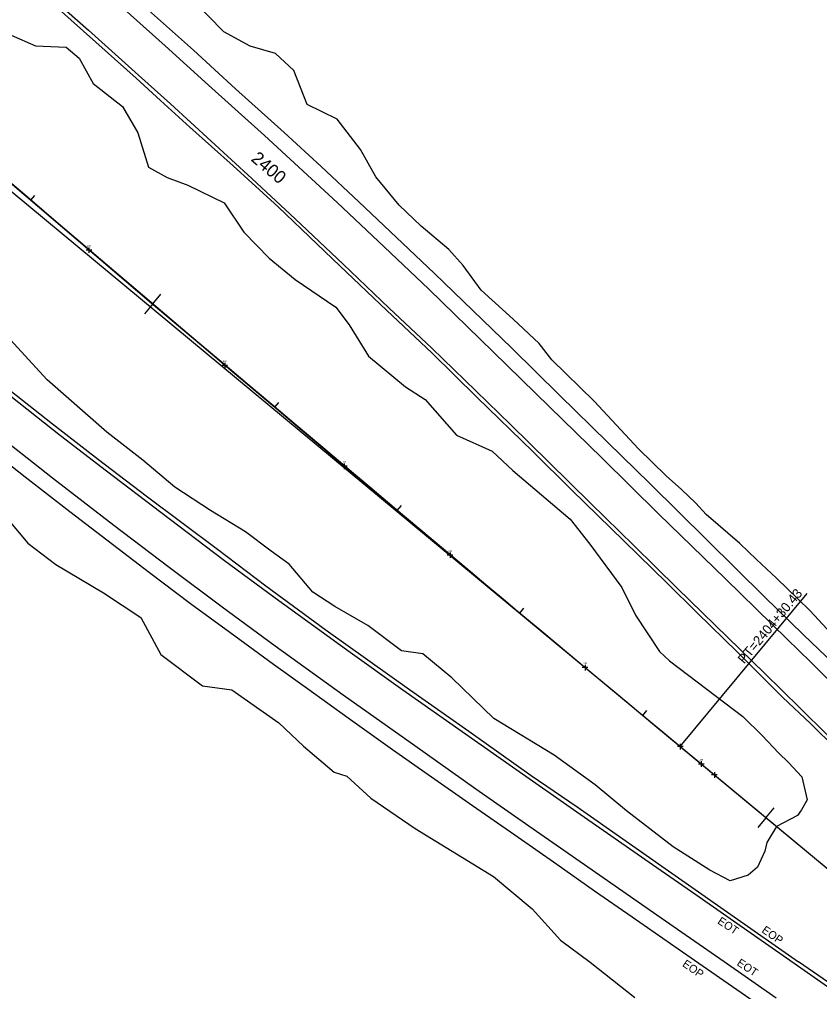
# Model space of a CAD drawing. Extents: x 2076109 to 2080761, y 592812 to 596750.
# Drawn here: x 2078513 to 2079013, y 594224 to 594832 of the extents above; entities that cross this region are included whole.
import ezdxf

# ---------------------------------------------------------------- set-up
doc = ezdxf.new("R2010")
doc.units = 0
for name, color, linetype in [('Default', 7, 'Continuous'), ('RD_EX_Misc', 7, 'Continuous'), ('RD_EX_Misc_txCode', 7, 'Continuous'), ('RD_EX_Road', 7, 'Continuous'), ('RD_EX_Road_txCode', 7, 'Continuous'), ('RD_EX_VEG', 7, 'Continuous'), ('RD_HC_Cl', 7, 'Continuous'), ('RD_HC_Data', 7, 'Continuous'), ('RD_HC_Data_Tic', 7, 'Continuous'), ('RD_HC_TX_Sta50', 7, 'Continuous')]:
    doc.layers.add(name, color=color, linetype=linetype)

msp = doc.modelspace()

# ---------------------------------------------------------------- linework, layer by layer
at = {"layer": 'Default'}
for p, q in [((2078420.27, 594797.03), (2079388.11, 593993.88)), ((2078420.27, 594797.03), (2079388.11, 593993.88)), ((2078453.96, 594769.07), (2079386.42, 593995.29)), ((2078453.96, 594769.07), (2079386.42, 593995.29)), ((2078556.81, 594689.1), (2078556.81, 594685.6)), ((2078556.81, 594689.1), (2078556.81, 594685.6)), ((2078558.56, 594687.35), (2078555.06, 594687.35)), ((2078558.56, 594687.35), (2078555.06, 594687.35)), ((2078641.75, 594616.99), (2078641.75, 594613.49)), ((2078641.75, 594616.99), (2078641.75, 594613.49)), ((2078643.5, 594615.24), (2078640, 594615.24)), ((2078643.5, 594615.24), (2078640, 594615.24)), ((2078718.12, 594552.24), (2078714.62, 594552.24)), ((2078718.12, 594552.24), (2078714.62, 594552.24)), ((2078716.37, 594553.99), (2078716.37, 594550.49)), ((2078716.37, 594553.99), (2078716.37, 594550.49)), ((2078784.23, 594496.7), (2078780.73, 594496.7)), ((2078784.23, 594496.7), (2078780.73, 594496.7)), ((2078782.48, 594498.45), (2078782.48, 594494.95)), ((2078782.48, 594498.45), (2078782.48, 594494.95)), ((2078866.86, 594428.21), (2078866.86, 594424.71)), ((2078866.86, 594428.21), (2078866.86, 594424.71)), ((2078868.61, 594426.46), (2078865.11, 594426.46)), ((2078868.61, 594426.46), (2078865.11, 594426.46)), ((2078926.37, 594378.79), (2078926.37, 594375.29)), ((2078926.37, 594378.79), (2078926.37, 594375.29)), ((2078928.12, 594377.04), (2078924.62, 594377.04)), ((2078928.12, 594377.04), (2078924.62, 594377.04)), ((2078939.53, 594367.93), (2078939.53, 594364.43)), ((2078939.53, 594367.93), (2078939.53, 594364.43)), ((2078941.28, 594366.18), (2078937.78, 594366.18)), ((2078941.28, 594366.18), (2078937.78, 594366.18)), ((2078947.68, 594361.11), (2078947.68, 594357.61)), ((2078947.68, 594361.11), (2078947.68, 594357.61)), ((2078949.43, 594359.36), (2078945.93, 594359.36)), ((2078949.43, 594359.36), (2078945.93, 594359.36))]:
    msp.add_line(p, q, dxfattribs=at)
for centre, radius, start, end in [((2104218.85, 624856.19), 39606.66, 228.410497, 230.313125), ((2104218.85, 624856.19), 39606.66, 228.410497, 230.313125), ((2104856.13, 625580.79), 40571.24, 228.501187, 230.313123), ((2104856.13, 625580.79), 40571.24, 228.501187, 230.313123)]:
    msp.add_arc(centre, radius, start, end, dxfattribs=at)
at = {"layer": 'RD_EX_Misc'}
for points in [[(2079094.25, 594345.43), (2079060.51, 594378.34), (2079032.44, 594405.76), (2079007.7, 594429.96), (2078993.11, 594444.28), (2078954.57, 594481.85), (2078912.78, 594522.62), (2078877.47, 594557.24), (2078844.61, 594589.49), (2078809.37, 594623.82), (2078769.18, 594662.95), (2078741.35, 594689.51), (2078711.92, 594717.07), (2078666.44, 594759.01), (2078631.5, 594790.54), (2078604.5, 594815.06), (2078565.16, 594850.51), (2078547.92, 594865.99)], [(2079094.25, 594345.43), (2079060.51, 594378.34), (2079032.44, 594405.76), (2079007.7, 594429.96), (2078993.11, 594444.28), (2078954.57, 594481.85), (2078912.78, 594522.62), (2078877.47, 594557.24), (2078844.61, 594589.49), (2078809.37, 594623.82), (2078769.18, 594662.95), (2078741.35, 594689.51), (2078711.92, 594717.07), (2078666.44, 594759.01), (2078631.5, 594790.54), (2078604.5, 594815.06), (2078565.16, 594850.51), (2078547.92, 594865.99)], [(2078527.36, 594850.61), (2078556.45, 594824.82), (2078587.87, 594796.74), (2078607.74, 594778.74), (2078633.15, 594755.53), (2078658.6, 594732.05), (2078685.78, 594706.83), (2078715.75, 594678.61), (2078744.45, 594651.12), (2078771.04, 594626.07), (2078798.58, 594599.38), (2078820.39, 594578.1), (2078844.01, 594555), (2078870.55, 594529.03), (2078897.28, 594502.85), (2078924.4, 594476.15), (2078955.99, 594445.27), (2078978.98, 594422.89), (2079001.06, 594401.33), (2079035.73, 594367.21), (2079059.39, 594344.16), (2079076.89, 594326.95)], [(2078527.36, 594850.61), (2078556.45, 594824.82), (2078587.87, 594796.74), (2078607.74, 594778.74), (2078633.15, 594755.53), (2078658.6, 594732.05), (2078685.78, 594706.83), (2078715.75, 594678.61), (2078744.45, 594651.12), (2078771.04, 594626.07), (2078798.58, 594599.38), (2078820.39, 594578.1), (2078844.01, 594555), (2078870.55, 594529.03), (2078897.28, 594502.85), (2078924.4, 594476.15), (2078955.99, 594445.27), (2078978.98, 594422.89), (2079001.06, 594401.33), (2079035.73, 594367.21), (2079059.39, 594344.16), (2079076.89, 594326.95)], [(2078999.59, 594239.98), (2078974.88, 594257.24), (2078936.08, 594284.49), (2078909.06, 594303.22), (2078861.75, 594336.14), (2078823.68, 594362.85), (2078790.15, 594386.24), (2078753.02, 594412.43), (2078719.99, 594435.94), (2078673.25, 594469.84), (2078640.78, 594493.89), (2078601.71, 594523.3), (2078567.81, 594549.12), (2078539.05, 594571.37), (2078502.91, 594599.8), (2078471.8, 594624.62), (2078428.5, 594659.86), (2078402.59, 594681.19)], [(2078999.59, 594239.98), (2078974.88, 594257.24), (2078936.08, 594284.49), (2078909.06, 594303.22), (2078861.75, 594336.14), (2078823.68, 594362.85), (2078790.15, 594386.24), (2078753.02, 594412.43), (2078719.99, 594435.94), (2078673.25, 594469.84), (2078640.78, 594493.89), (2078601.71, 594523.3), (2078567.81, 594549.12), (2078539.05, 594571.37), (2078502.91, 594599.8), (2078471.8, 594624.62), (2078428.5, 594659.86), (2078402.59, 594681.19)], [(2078384.22, 594665.44), (2078412.71, 594641.87), (2078439.7, 594619.98), (2078465.41, 594599.28), (2078499.3, 594572.31), (2078534.08, 594545.05), (2078572.27, 594515.47), (2078606.85, 594489.18), (2078640.01, 594464.5), (2078673.26, 594440.06), (2078715.65, 594409.47), (2078759.09, 594378.71), (2078798.64, 594350.77), (2078831.82, 594327.55), (2078876.03, 594296.78), (2078911.79, 594271.95), (2078953.79, 594242.84), (2078986.27, 594220.14)], [(2078384.22, 594665.44), (2078412.71, 594641.87), (2078439.7, 594619.98), (2078465.41, 594599.28), (2078499.3, 594572.31), (2078534.08, 594545.05), (2078572.27, 594515.47), (2078606.85, 594489.18), (2078640.01, 594464.5), (2078673.26, 594440.06), (2078715.65, 594409.47), (2078759.09, 594378.71), (2078798.64, 594350.77), (2078831.82, 594327.55), (2078876.03, 594296.78), (2078911.79, 594271.95), (2078953.79, 594242.84), (2078986.27, 594220.14)], [(2079606.82, 593782.2), (2079576.72, 593807.89), (2079549.76, 593830.63), (2079518.46, 593856.64), (2079487.66, 593881.52), (2079457.01, 593906.09), (2079428.71, 593928.55), (2079405.89, 593946.36), (2079378.4, 593967.67), (2079347.87, 593991.03), (2079317.43, 594014.17), (2079292.57, 594032.53), (2079270.33, 594048.83), (2079237.14, 594072.81), (2079210.84, 594091.53), (2079183.58, 594110.8), (2079158.5, 594128.52), (2079134.29, 594145.53), (2079108.18, 594163.72), (2079081.19, 594182.76), (2079043.3, 594209.43), (2078999.59, 594239.98)], [(2079606.82, 593782.2), (2079576.72, 593807.89), (2079549.76, 593830.63), (2079518.46, 593856.64), (2079487.66, 593881.52), (2079457.01, 593906.09), (2079428.71, 593928.55), (2079405.89, 593946.36), (2079378.4, 593967.67), (2079347.87, 593991.03), (2079317.43, 594014.17), (2079292.57, 594032.53), (2079270.33, 594048.83), (2079237.14, 594072.81), (2079210.84, 594091.53), (2079183.58, 594110.8), (2079158.5, 594128.52), (2079134.29, 594145.53), (2079108.18, 594163.72), (2079081.19, 594182.76), (2079043.3, 594209.43), (2078999.59, 594239.98)]]:
    msp.add_lwpolyline(points, dxfattribs=at)
at = {"layer": 'RD_EX_Road'}
for points in [[(2078558.22, 594869.34), (2078588.42, 594842.31), (2078622.08, 594812.23), (2078648.48, 594788.08), (2078678.77, 594760.79), (2078701.96, 594739.67), (2078725.53, 594717.48), (2078772.57, 594672.96), (2078821.14, 594626.17), (2078850.92, 594596.78), (2078881.03, 594567.06), (2078907.36, 594541.6), (2078978.96, 594470.6), (2079003.11, 594447.22), (2079027.27, 594424.11), (2079060.3, 594391.21), (2079082.75, 594369.01), (2079101.34, 594350.83)], [(2078558.22, 594869.34), (2078588.42, 594842.31), (2078622.08, 594812.23), (2078648.48, 594788.08), (2078678.77, 594760.79), (2078701.96, 594739.67), (2078725.53, 594717.48), (2078772.57, 594672.96), (2078821.14, 594626.17), (2078850.92, 594596.78), (2078881.03, 594567.06), (2078907.36, 594541.6), (2078978.96, 594470.6), (2079003.11, 594447.22), (2079027.27, 594424.11), (2079060.3, 594391.21), (2079082.75, 594369.01), (2079101.34, 594350.83)], [(2079075.83, 594324.41), (2079039.78, 594359.77), (2079007.66, 594391.49), (2078990.46, 594407.67), (2078962.09, 594436.18), (2078937, 594460.63), (2078917.93, 594479.34), (2078891.32, 594505.5), (2078858.31, 594537.65), (2078834.17, 594561.52), (2078799.48, 594595.2), (2078771.02, 594623.13), (2078742.92, 594649.7), (2078713.65, 594677.5), (2078699.51, 594691.16), (2078674.97, 594714.41), (2078646.9, 594739.94), (2078619.89, 594764.19), (2078601.61, 594780.93), (2078586.28, 594794.92), (2078528.26, 594846.85)], [(2079075.83, 594324.41), (2079039.78, 594359.77), (2079007.66, 594391.49), (2078990.46, 594407.67), (2078962.09, 594436.18), (2078937, 594460.63), (2078917.93, 594479.34), (2078891.32, 594505.5), (2078858.31, 594537.65), (2078834.17, 594561.52), (2078799.48, 594595.2), (2078771.02, 594623.13), (2078742.92, 594649.7), (2078713.65, 594677.5), (2078699.51, 594691.16), (2078674.97, 594714.41), (2078646.9, 594739.94), (2078619.89, 594764.19), (2078601.61, 594780.93), (2078586.28, 594794.92), (2078528.26, 594846.85)], [(2078403.91, 594683.55), (2078437.11, 594655.96), (2078473.88, 594626.4), (2078507.39, 594599.83), (2078533.94, 594578.82), (2078562.73, 594556.54), (2078592.52, 594533.73), (2078637.06, 594500.37), (2078667.28, 594477.57), (2078705.13, 594449.8), (2078757.08, 594412.68), (2078794.17, 594386.71), (2078833.25, 594359.03), (2078861.87, 594339.52), (2078957.95, 594272.17), (2079000.28, 594242.53)], [(2078403.91, 594683.55), (2078437.11, 594655.96), (2078473.88, 594626.4), (2078507.39, 594599.83), (2078533.94, 594578.82), (2078562.73, 594556.54), (2078592.52, 594533.73), (2078637.06, 594500.37), (2078667.28, 594477.57), (2078705.13, 594449.8), (2078757.08, 594412.68), (2078794.17, 594386.71), (2078833.25, 594359.03), (2078861.87, 594339.52), (2078957.95, 594272.17), (2079000.28, 594242.53)], [(2078977.34, 594214.19), (2078959.11, 594226.84), (2078925.13, 594250.42), (2078896.3, 594270.44), (2078872.84, 594286.82), (2078849.12, 594303.34), (2078823.04, 594321.78), (2078796.47, 594340.14), (2078768.74, 594359.44), (2078746.51, 594374.99), (2078718.8, 594394.87), (2078693.36, 594413.27), (2078672.13, 594428.44), (2078644.86, 594448.4), (2078620.36, 594466.36), (2078594.73, 594485.66), (2078571.44, 594503.37), (2078544.9, 594523.86), (2078516.99, 594545.43), (2078491.86, 594565.09), (2078457.22, 594592.46), (2078432.68, 594612.07), (2078397.93, 594640.6), (2078373.49, 594660.86)], [(2078977.34, 594214.19), (2078959.11, 594226.84), (2078925.13, 594250.42), (2078896.3, 594270.44), (2078872.84, 594286.82), (2078849.12, 594303.34), (2078823.04, 594321.78), (2078796.47, 594340.14), (2078768.74, 594359.44), (2078746.51, 594374.99), (2078718.8, 594394.87), (2078693.36, 594413.27), (2078672.13, 594428.44), (2078644.86, 594448.4), (2078620.36, 594466.36), (2078594.73, 594485.66), (2078571.44, 594503.37), (2078544.9, 594523.86), (2078516.99, 594545.43), (2078491.86, 594565.09), (2078457.22, 594592.46), (2078432.68, 594612.07), (2078397.93, 594640.6), (2078373.49, 594660.86)], [(2079021.75, 594227.81), (2079000.28, 594242.53)], [(2079021.75, 594227.81), (2079000.28, 594242.53)]]:
    msp.add_lwpolyline(points, dxfattribs=at)
at = {"layer": 'RD_EX_VEG'}
for points in [[(2079025.84, 594442.08), (2079007.51, 594461.99), (2078999.79, 594469.52), (2078986.48, 594482.41), (2078973.99, 594494.02), (2078963.49, 594503.92), (2078942.64, 594522.12), (2078936.16, 594529.31), (2078927.11, 594537.78), (2078917.6, 594546.29), (2078900.35, 594563.26), (2078872.61, 594592.97), (2078846.06, 594618.72), (2078838.25, 594629.06), (2078821.84, 594644.17), (2078801.94, 594662.3), (2078790.73, 594677.78), (2078781.67, 594687.79), (2078764.48, 594702.31), (2078750.72, 594715.53), (2078736.12, 594733.25), (2078726.62, 594750.23), (2078711.91, 594769.26), (2078693.21, 594778.43), (2078684.9, 594799.72), (2078673.35, 594810.33), (2078657.51, 594814.86), (2078641.14, 594823.71), (2078621.37, 594844.3)], [(2079025.84, 594442.08), (2079007.51, 594461.99), (2078999.79, 594469.52), (2078986.48, 594482.41), (2078973.99, 594494.02), (2078963.49, 594503.92), (2078942.64, 594522.12), (2078936.16, 594529.31), (2078927.11, 594537.78), (2078917.6, 594546.29), (2078900.35, 594563.26), (2078872.61, 594592.97), (2078846.06, 594618.72), (2078838.25, 594629.06), (2078821.84, 594644.17), (2078801.94, 594662.3), (2078790.73, 594677.78), (2078781.67, 594687.79), (2078764.48, 594702.31), (2078750.72, 594715.53), (2078736.12, 594733.25), (2078726.62, 594750.23), (2078711.91, 594769.26), (2078693.21, 594778.43), (2078684.9, 594799.72), (2078673.35, 594810.33), (2078657.51, 594814.86), (2078641.14, 594823.71), (2078621.37, 594844.3)], [(2078508.15, 594821.8), (2078523.36, 594815.05), (2078542.58, 594814.26), (2078550.75, 594807.29), (2078559.52, 594791.5), (2078577.86, 594777.14), (2078587.4, 594760.67), (2078594.03, 594739.22), (2078605.67, 594732.7), (2078618.6, 594727.87), (2078641.22, 594717), (2078653.58, 594698.57), (2078669.49, 594682.41), (2078685.64, 594668.96), (2078711.2, 594651.7), (2078719.5, 594640.73), (2078731.56, 594621.03), (2078754.68, 594601.99), (2078766.93, 594593.91), (2078786.62, 594571.72), (2078808.84, 594561.74), (2078821.7, 594549.64), (2078857.52, 594519.18), (2078869.76, 594503.55), (2078889.93, 594476.54), (2078898.33, 594459.23), (2078913.3, 594436.47), (2078919.61, 594430.71), (2078965.5, 594395.87), (2078977.45, 594384), (2078987.83, 594373.1), (2078994.04, 594367.23), (2079002.39, 594358.25), (2079005.69, 594343.82), (2079002.21, 594337.59), (2078999.71, 594334.02), (2078986.55, 594327.04), (2078980.37, 594317.23), (2078979.12, 594311.67), (2078974.72, 594301.8), (2078968.87, 594296.68), (2078957.53, 594293.11), (2078944.81, 594299.76), (2078922.02, 594314.46), (2078892.67, 594336.99), (2078873.15, 594353.14), (2078847.58, 594371.69), (2078809.86, 594394.56), (2078783.56, 594420.01), (2078765.51, 594435.08), (2078752.06, 594437.01), (2078731.17, 594452.85), (2078710.5, 594464.64), (2078696.71, 594473.49), (2078682.04, 594491), (2078670.59, 594499.14), (2078654.56, 594511.2), (2078632.76, 594524.68), (2078610.49, 594539.13), (2078590.41, 594556.12), (2078568, 594573.63), (2078530.61, 594606.35), (2078507.51, 594631.45)], [(2078508.15, 594821.8), (2078523.36, 594815.05), (2078542.58, 594814.26), (2078550.75, 594807.29), (2078559.52, 594791.5), (2078577.86, 594777.14), (2078587.4, 594760.67), (2078594.03, 594739.22), (2078605.67, 594732.7), (2078618.6, 594727.87), (2078641.22, 594717), (2078653.58, 594698.57), (2078669.49, 594682.41), (2078685.64, 594668.96), (2078711.2, 594651.7), (2078719.5, 594640.73), (2078731.56, 594621.03), (2078754.68, 594601.99), (2078766.93, 594593.91), (2078786.62, 594571.72), (2078808.84, 594561.74), (2078821.7, 594549.64), (2078857.52, 594519.18), (2078869.76, 594503.55), (2078889.93, 594476.54), (2078898.33, 594459.23), (2078913.3, 594436.47), (2078919.61, 594430.71), (2078965.5, 594395.87), (2078977.45, 594384), (2078987.83, 594373.1), (2078994.04, 594367.23), (2079002.39, 594358.25), (2079005.69, 594343.82), (2079002.21, 594337.59), (2078999.71, 594334.02), (2078986.55, 594327.04), (2078980.37, 594317.23), (2078979.12, 594311.67), (2078974.72, 594301.8), (2078968.87, 594296.68), (2078957.53, 594293.11), (2078944.81, 594299.76), (2078922.02, 594314.46), (2078892.67, 594336.99), (2078873.15, 594353.14), (2078847.58, 594371.69), (2078809.86, 594394.56), (2078783.56, 594420.01), (2078765.51, 594435.08), (2078752.06, 594437.01), (2078731.17, 594452.85), (2078710.5, 594464.64), (2078696.71, 594473.49), (2078682.04, 594491), (2078670.59, 594499.14), (2078654.56, 594511.2), (2078632.76, 594524.68), (2078610.49, 594539.13), (2078590.41, 594556.12), (2078568, 594573.63), (2078530.61, 594606.35), (2078507.51, 594631.45)], [(2078507.8, 594517.14), (2078518.72, 594504.3), (2078536.04, 594490.95), (2078565.92, 594473.13), (2078589.16, 594457.67), (2078601.68, 594434.63), (2078627.82, 594415.03), (2078646.18, 594412.59), (2078675.48, 594391.94), (2078690.92, 594377.26), (2078710.14, 594361.19), (2078718.08, 594358.63), (2078732.96, 594344.81), (2078760.63, 594325.92), (2078809.64, 594295.79), (2078833.84, 594275.64), (2078851.54, 594256.08), (2078869.99, 594242.33), (2078898.02, 594220.2)], [(2078507.8, 594517.14), (2078518.72, 594504.3), (2078536.04, 594490.95), (2078565.92, 594473.13), (2078589.16, 594457.67), (2078601.68, 594434.63), (2078627.82, 594415.03), (2078646.18, 594412.59), (2078675.48, 594391.94), (2078690.92, 594377.26), (2078710.14, 594361.19), (2078718.08, 594358.63), (2078732.96, 594344.81), (2078760.63, 594325.92), (2078809.64, 594295.79), (2078833.84, 594275.64), (2078851.54, 594256.08), (2078869.99, 594242.33), (2078898.02, 594220.2)]]:
    msp.add_lwpolyline(points, dxfattribs=at)
at = {"layer": 'RD_HC_Cl'}
msp.add_line((2078926.37, 594377.04), (2079262.4, 594098.2), dxfattribs=at)
msp.add_line((2078926.37, 594377.04), (2079262.4, 594098.2), dxfattribs=at)
msp.add_arc((2104218.85, 624856.19), 39606.66, 228.410497, 230.313125, dxfattribs=at)
msp.add_arc((2104218.85, 624856.19), 39606.66, 228.410497, 230.313125, dxfattribs=at)
at = {"layer": 'RD_HC_Data'}
msp.add_line((2078926.37, 594377.04), (2079005.74, 594472.69), dxfattribs=at)
msp.add_line((2078926.37, 594377.04), (2079005.74, 594472.69), dxfattribs=at)
at = {"layer": 'RD_HC_Data_Tic'}
for p, q in [((2078520.46, 594718.5), (2078523.06, 594721.54)), ((2078520.46, 594718.5), (2078523.06, 594721.54)), ((2078596.64, 594653.71), (2078601.81, 594659.81)), ((2078596.64, 594653.71), (2078601.81, 594659.81)), ((2078596.64, 594653.71), (2078591.46, 594647.61)), ((2078596.64, 594653.71), (2078591.46, 594647.61)), ((2078672.97, 594589.11), (2078675.55, 594592.17)), ((2078672.97, 594589.11), (2078675.55, 594592.17)), ((2078749.47, 594524.71), (2078752.05, 594527.78)), ((2078749.47, 594524.71), (2078752.05, 594527.78)), ((2078826.14, 594460.5), (2078828.7, 594463.57)), ((2078826.14, 594460.5), (2078828.7, 594463.57)), ((2078902.96, 594396.49), (2078905.52, 594399.56)), ((2078902.96, 594396.49), (2078905.52, 594399.56)), ((2078979.91, 594332.62), (2078985.02, 594338.78)), ((2078979.91, 594332.62), (2078985.02, 594338.78)), ((2078979.91, 594332.62), (2078974.8, 594326.46)), ((2078979.91, 594332.62), (2078974.8, 594326.46))]:
    msp.add_line(p, q, dxfattribs=at)

# ---------------------------------------------------------------- texts
at = {"layer": 'Default'}
for s, p in [('239', (2078555.63, 594689.55)), ('239', (2078555.63, 594689.55)), ('240', (2078640.53, 594617.44)), ('240', (2078640.53, 594617.44)), ('241', (2078715.47, 594554.44)), ('241', (2078715.47, 594554.44)), ('242', (2078781.3, 594498.9)), ('242', (2078781.3, 594498.9)), ('243', (2078865.68, 594428.66)), ('243', (2078865.68, 594428.66)), ('244', (2078938.35, 594368.38)), ('244', (2078938.35, 594368.38))]:
    msp.add_text(s, height=1, dxfattribs=at).set_placement(p)
at = {"layer": 'RD_EX_Misc_txCode'}
for p in [(2078949.2, 594266.85), (2078949.2, 594266.85), (2078961.31, 594240.75), (2078961.31, 594240.75)]:
    msp.add_text('EOT', height=5, rotation=326.48137, dxfattribs=at).set_placement(p)
at = {"layer": 'RD_EX_Road_txCode'}
for p in [(2078976.83, 594261.33), (2078976.83, 594261.33), (2078927.26, 594240.19), (2078927.26, 594240.19)]:
    msp.add_text('EOP', height=5, rotation=325.02682, dxfattribs=at).set_placement(p)
at = {"layer": 'RD_HC_Data'}
msp.add_text('PT=2404+30.43', height=6, rotation=50.31313, dxfattribs=at).set_placement((2078966.34, 594428.34))
msp.add_text('PT=2404+30.43', height=6, rotation=50.31313, dxfattribs=at).set_placement((2078966.34, 594428.34))
at = {"layer": 'RD_HC_TX_Sta50'}
msp.add_text('2400', height=8, rotation=319.69045, dxfattribs=at).set_placement((2078657.6, 594743.62))
msp.add_text('2400', height=8, rotation=319.69045, dxfattribs=at).set_placement((2078657.6, 594743.62))

doc.saveas('drawing.dxf')
